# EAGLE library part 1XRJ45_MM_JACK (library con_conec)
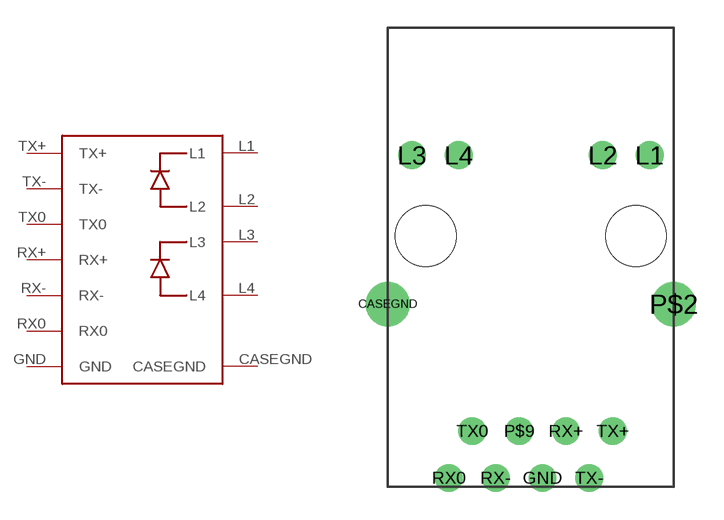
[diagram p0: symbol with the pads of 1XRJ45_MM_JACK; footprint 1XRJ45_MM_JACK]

Designator prefix -

## 1XRJ45_MM_JACK  [1XRJ45_MM_JACK]
CASEGND  CASEGND
GND  GND
L1  L1
L2  L2
L3  L3
L4  L4
RX0  RX0
RX+  RX+
RX-  RX-
TX0  TX0
TX+  TX+
TX-  TX-

## Footprint 1XRJ45_MM_JACK (pad centres in mm)
drill 1.6 round: CASEGND -7.75,-3.7; P$2 7.75,-3.7
drill 1 round: GND 0.635,-13.13; L1 6.44,4.38; L2 3.9,4.38; L3 -6.44,4.38; L4 -3.9,4.38; P$9 -0.635,-10.59; RX0 -4.445,-13.13; RX+ 1.905,-10.59; RX- -1.905,-13.13; TX0 -3.175,-10.59; TX+ 4.445,-10.59; TX- 3.175,-13.13
hole 3.3 at 5.7,0
hole 3.3 at -5.7,0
